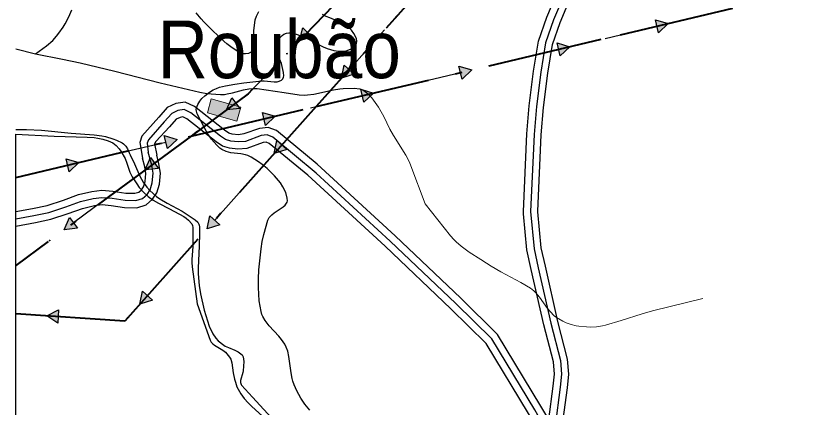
# Model space of a CAD drawing. Extents: x -64005 to -55000, y -89025 to -80000.
# Drawn here: x -64000 to -62912, y -85720 to -85176 of the extents above; entities that cross this region are included whole.
import ezdxf
from ezdxf.enums import TextEntityAlignment as Align

# ---------------------------------------------------------------- set-up
doc = ezdxf.new("R2010")
doc.units = 0
doc.header["$LTSCALE"] = 32
doc.linetypes.add('DOT_DASHED', pattern=[7.7, 5, -1.2, 0.3, -1.2])
doc.linetypes.add('LONG_DASHED', pattern=[7.5, 6, -1.5])
for name, color, linetype, lineweight in [('18', 7, 'Continuous', 25), ('2', 7, 'Continuous', 25), ('24', 7, 'Continuous', 25), ('39', 7, 'LONG_DASHED', 25), ('7', 7, 'Continuous', 13), ('8', 7, 'Continuous', 25)]:
    doc.layers.add(name, color=color, linetype=linetype, lineweight=lineweight)
doc.layers.add('45', color=7, linetype='Continuous')

msp = doc.modelspace()

# ---------------------------------------------------------------- hatches: boundary and pattern name
at = {"layer": '18'}
for points in [[(-63112.58, -85182.02), (-63094.86, -85187.34), (-63108.33, -85200.03)], [(-63588.59, -85206.01), (-63606.37, -85211.13), (-63601.91, -85193.17)], [(-63248.84, -85214.18), (-63231.12, -85219.5), (-63244.59, -85232.19)], [(-63530.68, -85257.56), (-63548.25, -85263.37), (-63544.49, -85245.25)], [(-63385.09, -85246.34), (-63367.38, -85251.66), (-63380.84, -85264.34)], [(-63521.35, -85278.49), (-63503.63, -85283.82), (-63517.1, -85296.5)], [(-63689.25, -85305.16), (-63707.63, -85307.24), (-63700.24, -85290.28)], [(-63657.61, -85310.65), (-63639.89, -85315.97), (-63653.36, -85328.65)], [(-63793.87, -85342.8), (-63776.15, -85348.12), (-63789.62, -85360.8)], [(-63623.84, -85362.07), (-63641.41, -85367.87), (-63637.65, -85349.76)], [(-63930.12, -85374.95), (-63912.41, -85380.28), (-63925.87, -85392.96)], [(-63801.85, -85388.35), (-63820.23, -85390.43), (-63812.85, -85373.47)], [(-63914.45, -85471.55), (-63932.84, -85473.63), (-63925.45, -85456.67)], [(-63717, -85466.57), (-63734.57, -85472.37), (-63730.81, -85454.26)], [(-63810.17, -85571.07), (-63827.73, -85576.88), (-63823.98, -85558.76)], [(-63941.65, -85603.3), (-63957.02, -85593), (-63940.42, -85584.84)]]:
    msp.add_hatch(color=256, dxfattribs=at).paths.add_polyline_path(points)
at = {"layer": '7'}
msp.add_hatch(color=256, dxfattribs=at).paths.add_polyline_path([(-63687.75, -85303.56), (-63728.64, -85291.98), (-63734.09, -85311.22), (-63693.2, -85322.8)])

# ---------------------------------------------------------------- linework, layer by layer
at = {"layer": '18'}
for p, q in [((-63543.92, -85146.32), (-63595.25, -85199.59)), ((-63488.36, -85196.18), (-63537.59, -85251.41)), ((-63318.71, -85240.18), (-63246.71, -85223.18)), ((-63454.97, -85272.33), (-63382.97, -85255.34)), ((-63727.49, -85336.64), (-63655.48, -85319.65)), ((-63863.74, -85368.79), (-63791.74, -85351.8)), ((-64000, -85400.95), (-63928, -85383.96)), ((-63674.68, -85405.19), (-63723.91, -85460.42)), ((-63860.45, -85420.14), (-63919.95, -85464.11)), ((-63973.05, -85503.34), (-64000, -85523.25)), ((-63767.84, -85509.7), (-63817.07, -85564.92)), ((-63867.22, -85598.99), (-63941.03, -85594.07))]:
    msp.add_line(p, q, dxfattribs=at)
at = {"layer": '18', "linetype": 'DOT_DASHED', "lineweight": 40}
for points in [[(-62369.26, -83445.65), (-62236.29, -83546.11), (-62227.39, -83552.83), (-62158.46, -83621.75), (-62183.05, -83848.43), (-62289.57, -83955.78), (-62419.8, -84087.01), (-63204.55, -84877.81), (-63379.7, -85074.29), (-63583.22, -85302.6), (-63848.56, -85600.24), (-64000, -85590.13)], [(-62600.64, -83578.59), (-62627.36, -83673.57), (-62637.7, -84129.6), (-62639.47, -84207.74), (-63103.07, -84688.84), (-63500.32, -85101.08), (-63677.61, -85285.06), (-63756.78, -85343.55), (-64000, -85523.25)], [(-64000, -85400.95), (-63756.78, -85343.55), (-63583.22, -85302.6), (-63160.94, -85202.94), (-62774.07, -85111.63), (-62063.05, -84888.71), (-61746.39, -84828.12), (-61731.7, -84825.31), (-61594.06, -84786.87), (-61360.14, -84721.55), (-60481.8, -84478.68), (-59562.86, -84105.04), (-59208.4, -83960.92), (-58840.52, -84105.61)]]:
    msp.add_lwpolyline(points, dxfattribs=at)
at = {"layer": '18'}
for points in [[(-63112.58, -85182.02), (-63094.86, -85187.34), (-63108.33, -85200.03)], [(-63588.59, -85206.01), (-63606.37, -85211.13), (-63601.91, -85193.17)], [(-63248.84, -85214.18), (-63231.12, -85219.5), (-63244.59, -85232.19)], [(-63530.68, -85257.56), (-63548.25, -85263.37), (-63544.49, -85245.25)], [(-63385.09, -85246.34), (-63367.38, -85251.66), (-63380.84, -85264.34)], [(-63521.35, -85278.49), (-63503.63, -85283.82), (-63517.1, -85296.5)], [(-63689.25, -85305.16), (-63707.63, -85307.24), (-63700.24, -85290.28)], [(-63657.61, -85310.65), (-63639.89, -85315.97), (-63653.36, -85328.65)], [(-63793.87, -85342.8), (-63776.15, -85348.12), (-63789.62, -85360.8)], [(-63623.84, -85362.07), (-63641.41, -85367.87), (-63637.65, -85349.76)], [(-63930.12, -85374.95), (-63912.41, -85380.28), (-63925.87, -85392.96)], [(-63801.85, -85388.35), (-63820.23, -85390.43), (-63812.85, -85373.47)], [(-63914.45, -85471.55), (-63932.84, -85473.63), (-63925.45, -85456.67)], [(-63717, -85466.57), (-63734.57, -85472.37), (-63730.81, -85454.26)], [(-63810.17, -85571.07), (-63827.73, -85576.88), (-63823.98, -85558.76)], [(-63941.65, -85603.3), (-63957.02, -85593), (-63940.42, -85584.84)]]:
    msp.add_lwpolyline(points, close=True, dxfattribs=at)
for points in [[(-63182.46, -85208.02), (-63160.94, -85202.94), (-63110.45, -85191.02)], [(-63641.06, -85247.13), (-63677.61, -85285.06), (-63694.75, -85297.72)], [(-63591.23, -85304.49), (-63583.22, -85302.6), (-63519.22, -85287.5)], [(-63581.52, -85300.69), (-63583.22, -85302.6), (-63630.75, -85355.91)], [(-63747.85, -85336.95), (-63756.78, -85343.55), (-63807.35, -85380.91)]]:
    msp.add_lwpolyline(points, dxfattribs=at)
for centre in [(-63471.72, -85177.52), (-63070.53, -85181.6), (-63206.79, -85213.76), (-63623.71, -85229.13), (-63343.05, -85245.92), (-63564.88, -85282.03), (-63479.3, -85278.07), (-63615.56, -85310.23), (-63727.74, -85322.1), (-63751.82, -85342.38), (-63888.08, -85374.53), (-63658.04, -85386.53), (-63840.34, -85405.29), (-63952.94, -85488.48), (-63751.2, -85491.03), (-63981.96, -85591.34), (-63844.37, -85595.54)]:
    msp.add_circle(centre, 0.5, dxfattribs=at)
at = {"layer": '2'}
msp.add_line((-64000, -85222.42), (-63972.52, -85229.46), dxfattribs=at)
for points in [[(-63972.52, -85229.46), (-63957.24, -85218.27), (-63948.46, -85210.72), (-63943.24, -85205), (-63939.99, -85200.91), (-63934, -85192.18), (-63931.23, -85187.55), (-63926.36, -85178.12), (-63922.31, -85168.46)], [(-63972.52, -85229.46), (-63934.93, -85236.88), (-63910.67, -85242.04), (-63862.42, -85253.64), (-63799.49, -85269.67), (-63744.58, -85282.66), (-63735.07, -85284.37), (-63728.67, -85285.09), (-63715.92, -85285.84), (-63710.29, -85285.63), (-63706.54, -85285.11), (-63699.04, -85283.44), (-63684.04, -85279.27), (-63676.53, -85277.76), (-63669.02, -85277.3), (-63665.26, -85277.61), (-63627.57, -85283.15), (-63606.64, -85286.08), (-63599.88, -85286.53), (-63595.37, -85286.39), (-63586.35, -85285.26), (-63559.29, -85279.27), (-63550.27, -85277.88), (-63545.76, -85277.54), (-63530.42, -85277), (-63522.85, -85278.12), (-63518.01, -85279.99), (-63515.67, -85281.36), (-63512.3, -85284.06), (-63506.19, -85290.39)], [(-64000, -85334.63), (-63984.87, -85334.55), (-63964.19, -85335.42), (-63922.93, -85339.54), (-63891.15, -85341.8), (-63880.66, -85343.21), (-63875.45, -85344.25), (-63865.12, -85347.22), (-63860.01, -85349.25), (-63852.43, -85353.08), (-63850.49, -85354.41), (-63847.4, -85357.64), (-63845.04, -85361.41), (-63842.4, -85366.81), (-63841.04, -85369.48), (-63835.11, -85382.12), (-63827.74, -85399.12), (-63823.24, -85407.29), (-63817.86, -85414.65), (-63813.78, -85419.13), (-63804.73, -85427.26), (-63800.01, -85430.77), (-63790.02, -85436.78), (-63769.27, -85447.62), (-63759.27, -85454.03), (-63751.03, -85459.87), (-63747.52, -85463.21), (-63745.87, -85465.74), (-63745.32, -85467.12), (-63744.93, -85469.34), (-63744.83, -85478.37), (-63745.64, -85496.45), (-63747.06, -85526.41), (-63747.04, -85534.6), (-63745.66, -85550.98), (-63743.84, -85562.5), (-63738.54, -85585.22), (-63734.16, -85600.08), (-63731.44, -85607.32), (-63726.44, -85618.03), (-63722.34, -85624.08), (-63719.04, -85627.59), (-63711.49, -85633.73), (-63709.42, -85635.06), (-63705.03, -85637.15), (-63695.91, -85640.66), (-63691.55, -85643), (-63687.66, -85645.66), (-63686, -85647.22), (-63684.43, -85650.13), (-63683.66, -85656.54), (-63684.43, -85669.39), (-63684.74, -85671.66), (-63687.94, -85682.56), (-63688.12, -85685.46), (-63687.38, -85688.14), (-63686.57, -85689.36), (-63671.62, -85705.77), (-63640.29, -85740)]]:
    msp.add_lwpolyline(points, dxfattribs=at)
at = {"layer": '2', "lineweight": 13}
msp.add_lwpolyline([(-63046.65, -85568.95), (-63116.44, -85586.08), (-63131.11, -85590.11), (-63160.11, -85599.43), (-63181.94, -85606.06), (-63185.94, -85607.01), (-63194.12, -85608.21), (-63202.42, -85608.59), (-63207.97, -85608.47), (-63218.97, -85607.49), (-63222.57, -85606.93), (-63229.63, -85605.21), (-63236.5, -85602.69), (-63240.96, -85600.59), (-63249.59, -85595.37), (-63252.92, -85592.8), (-63258.76, -85586.98), (-63262.22, -85582.74), (-63273.3, -85567.27), (-63278.41, -85561.16), (-63281.22, -85558.38), (-63285.9, -85554.71), (-63299.2, -85546.58), (-63326.89, -85531.78), (-63340.53, -85523.99), (-63347.13, -85519.76), (-63354.95, -85514.68), (-63370.79, -85504.6), (-63382.16, -85496.45), (-63389.16, -85490.44), (-63392.43, -85487.19), (-63396.97, -85481.97), (-63431.86, -85437.74), (-63451.88, -85384.62), (-63453.94, -85379.67), (-63458.86, -85370.15), (-63476.04, -85342.73), (-63480.83, -85333.9), (-63489.39, -85316.3), (-63496.63, -85303.24), (-63506.19, -85290.39)], dxfattribs=at)
at = {"layer": '24'}
for points in [[(-63663.37, -85171.32), (-63666.6, -85177.59), (-63668.11, -85182.81), (-63670.11, -85196.81), (-63669.93, -85213.21), (-63670.33, -85217.89), (-63671.4, -85222.52), (-63672.27, -85224.82), (-63673.38, -85226.54), (-63674.39, -85227.45), (-63676.89, -85228.75), (-63681.39, -85229.48), (-63684.85, -85229.2), (-63687.43, -85228.52), (-63689.9, -85227.34), (-63701.36, -85219.58), (-63707, -85215.33), (-63715.09, -85208.45), (-63731.22, -85193.05), (-63739.02, -85185.15), (-63742.77, -85181.04), (-63749.72, -85172.32)], [(-63638.83, -85218.72), (-63637.86, -85214.28), (-63636.02, -85210.34), (-63633.17, -85206.52), (-63630.27, -85203.74), (-63628.08, -85202.25), (-63624.3, -85200.74), (-63621.2, -85200.27), (-63618.84, -85200.29), (-63614.09, -85201.05), (-63609.39, -85202.49), (-63596.56, -85207.53), (-63573.28, -85219.67), (-63567.95, -85221.96), (-63558.85, -85224.61), (-63555.56, -85225.2), (-63550.59, -85225.7), (-63545.64, -85225.67), (-63541.39, -85225.11), (-63535.52, -85222.97), (-63531.32, -85220.3), (-63528.04, -85217.03), (-63527.12, -85215.15), (-63526.72, -85211.63), (-63527.29, -85208.56), (-63528.92, -85204.56), (-63530.82, -85201.35), (-63534.37, -85196.76), (-63537.04, -85193.98), (-63542.56, -85189.54), (-63548.8, -85186.07), (-63564.38, -85179.65), (-63569.44, -85177.39), (-63574.26, -85174.72)], [(-63592.16, -85723.99), (-63598.7, -85715.79), (-63604.39, -85707.22), (-63609.85, -85697.25), (-63613.7, -85688.91), (-63615.65, -85683.52), (-63616.63, -85679.83), (-63618.05, -85672.27), (-63620.95, -85649.36), (-63622.62, -85642.07), (-63624.64, -85636.46), (-63626.73, -85632.43), (-63631.12, -85626.08), (-63635.21, -85621.23), (-63648.35, -85606.99), (-63654.09, -85599.49), (-63657.13, -85594.14), (-63658.34, -85591.34), (-63659.67, -85586.92), (-63662.21, -85571.98), (-63663.4, -85553.77), (-63663.3, -85541.55), (-63662.66, -85529.32), (-63659.64, -85500.02), (-63657.93, -85489.95), (-63655.73, -85479.94), (-63650.22, -85460.34), (-63648.29, -85456.57), (-63644.9, -85452.89), (-63641.55, -85450.23), (-63629.02, -85441.84), (-63626.22, -85439.4), (-63624.2, -85436.81), (-63623.56, -85435.44), (-63623.16, -85433.26), (-63623.39, -85429.69), (-63625.5, -85421.98), (-63629.41, -85413.91), (-63632.8, -85408.57), (-63635.31, -85405.11), (-63640.79, -85398.63), (-63651.19, -85388.58), (-63658.33, -85382.83), (-63663.23, -85379.32), (-63673.53, -85372.81), (-63678.05, -85370.7), (-63681.24, -85369.71), (-63687.89, -85368.41), (-63701.54, -85366.62), (-63708.1, -85365.02), (-63714.19, -85362.23), (-63716.99, -85360.21), (-63721.18, -85356.37), (-63728.31, -85348), (-63734.24, -85338.88), (-63748.08, -85312.56), (-63749.21, -85309.12), (-63749.48, -85306.87), (-63749.1, -85304.17), (-63747.26, -85299.79), (-63744.42, -85295.13), (-63741.6, -85291.6), (-63737.52, -85287.5), (-63731.3, -85282.67), (-63725.86, -85279.44), (-63721.61, -85277.44), (-63717.27, -85275.85), (-63708.8, -85273.68), (-63696.22, -85271.32), (-63683.63, -85269.64), (-63658.42, -85267.01), (-63655.42, -85266.9), (-63641.29, -85268.46), (-63637.28, -85268.15), (-63634.62, -85267.42), (-63631.34, -85265.74), (-63629.55, -85264.11), (-63628.4, -85261.94), (-63628, -85259.99), (-63628.33, -85255.17), (-63631.36, -85243), (-63637.84, -85227.46), (-63638.9, -85222.29), (-63638.83, -85218.72)], [(-63972.31, -87227.87), (-63975.53, -87229.32), (-64000, -87237.1), (-64000, -85340.91)], [(-64000, -85340.91), (-63946.82, -85343.87), (-63900.86, -85345.13), (-63891.04, -85345.72), (-63886.16, -85346.29), (-63878.9, -85347.68), (-63871.69, -85349.92), (-63865.33, -85352.91), (-63860.52, -85356.65), (-63856.49, -85361.19), (-63854.13, -85364.53), (-63848.25, -85374.62), (-63845.78, -85380.97), (-63841.51, -85393.83), (-63838.51, -85399.9), (-63832.03, -85409.89), (-63828.52, -85414.68), (-63822.77, -85421.42), (-63816.27, -85427.45), (-63809.1, -85432.47), (-63801.74, -85436.66), (-63786.71, -85444.29), (-63766.99, -85455.23), (-63763.62, -85457.46), (-63760.4, -85460.08), (-63755.85, -85465.3), (-63754.81, -85467.74), (-63754.32, -85470.28), (-63754.13, -85475.46), (-63754.13, -85496.87), (-63755.62, -85514.75), (-63755.77, -85518.94), (-63755.39, -85525.21), (-63748.47, -85576.21), (-63730.21, -85626.59), (-63728.76, -85629.36), (-63726.46, -85631.91), (-63724.21, -85633.65), (-63712.46, -85640.47), (-63709, -85643.22), (-63703.48, -85650.4), (-63701.78, -85653.33), (-63699.98, -85658.07), (-63698.1, -85671.93), (-63696.34, -85680.69), (-63695.26, -85685.03), (-63693.06, -85691.45), (-63691.47, -85694.93), (-63687.7, -85701.48), (-63683.27, -85707.56), (-63677.72, -85713.82), (-63672.91, -85718.52), (-63657.12, -85732.6)]]:
    msp.add_lwpolyline(points, dxfattribs=at)
at = {"layer": '39'}
for points in [[(-63241.08, -85151.48), (-63254.08, -85182.26), (-63265.23, -85214.1), (-63271.6, -85254.69), (-63277.71, -85302.71), (-63280.89, -85341.17), (-63285.66, -85448.09), (-63280.88, -85500.08), (-63275.05, -85526.35), (-63257.81, -85603.02), (-63244.28, -85655.02), (-63242.69, -85673.85), (-63244.55, -85691.89), (-63251.71, -85746.02)], [(-63583.07, -85394.9), (-63643.43, -85344.82), (-63651.14, -85341.98), (-63659.26, -85342.79), (-63681.18, -85350.91), (-63691.33, -85351.73), (-63701.47, -85350.51), (-63708.78, -85348.48), (-63716.09, -85343.6), (-63757.08, -85311.12), (-63766.42, -85306.65), (-63774.94, -85307.87), (-63783.58, -85312.13), (-63794.06, -85323.85), (-63815.96, -85348.53), (-63817.5, -85353.47), (-63816.04, -85365.74)], [(-64000, -85458.45), (-63974.64, -85453.86), (-63953.86, -85449.41), (-63930.6, -85441.74), (-63910.07, -85434.3), (-63892.5, -85430.09), (-63880.38, -85428.61), (-63866.28, -85429.85), (-63848.21, -85432.57), (-63833.36, -85433.05), (-63823.96, -85430.08), (-63817.77, -85424.64), (-63813.57, -85418.21), (-63810.6, -85408.31), (-63809.36, -85395.19), (-63811.09, -85384.05), (-63816.04, -85365.74)], [(-63253.9, -85768.32), (-63280.08, -85723.39), (-63339.56, -85625.07), (-63389.57, -85575.91), (-63480.62, -85489.18), (-63583.07, -85394.9)]]:
    msp.add_lwpolyline(points, dxfattribs=at)
at = {"layer": '7'}
msp.add_lwpolyline([(-63687.75, -85303.56), (-63728.64, -85291.98), (-63734.09, -85311.22), (-63693.2, -85322.8)], close=True, dxfattribs=at)
at = {"layer": '8', "linetype": 'LONG_DASHED'}
for points in [[(-63260.6, -85736.96), (-63254.48, -85690.72), (-63252.73, -85673.76), (-63254.17, -85656.71), (-63267.53, -85605.38), (-63284.81, -85528.54), (-63290.78, -85501.64), (-63295.41, -85451.26), (-63295.68, -85448.33), (-63290.87, -85340.53), (-63287.66, -85301.67), (-63281.51, -85253.28), (-63274.97, -85211.65), (-63263.41, -85178.66), (-63250.54, -85148.18)], [(-63582.03, -85382.29), (-63638.39, -85336.02), (-63649.84, -85331.8), (-63661.66, -85332.98), (-63683.61, -85340.36), (-63690.73, -85341.73), (-63699.52, -85340.67), (-63704.56, -85339.27), (-63710.2, -85335.51), (-63751.75, -85302.58), (-63764.84, -85296.32), (-63777.93, -85298.2), (-63789.74, -85304.02), (-63801.53, -85317.2), (-63824.87, -85343.5), (-63827.68, -85352.53), (-63823.95, -85374.34)], [(-64000, -85448.29), (-63976.58, -85444.05), (-63956.48, -85439.74), (-63933.87, -85432.29), (-63912.95, -85424.71), (-63894.28, -85420.23), (-63880.55, -85418.56), (-63865.1, -85419.92), (-63847.3, -85422.59), (-63834.74, -85423), (-63828.98, -85421.18), (-63825.4, -85418.03), (-63822.73, -85413.95), (-63820.46, -85406.38), (-63819.43, -85395.49), (-63820.89, -85386.08), (-63823.95, -85374.34)], [(-63260.6, -85736.96), (-63271.48, -85718.28), (-63331.65, -85618.82), (-63382.62, -85568.72), (-63473.78, -85481.88), (-63582.03, -85382.29)]]:
    msp.add_lwpolyline(points, dxfattribs=at)
at = {"layer": '8'}
for points in [[(-63241.77, -85747.16), (-63234.62, -85693.06), (-63232.65, -85673.94), (-63234.39, -85653.33), (-63248.09, -85600.66), (-63265.29, -85524.17), (-63270.98, -85498.53), (-63275.58, -85448.53), (-63275.64, -85447.85), (-63270.91, -85341.81), (-63267.76, -85303.75), (-63261.7, -85256.09), (-63255.49, -85216.55), (-63244.75, -85185.86), (-63231.62, -85154.79)], [(-63594.73, -85397.75), (-63648.47, -85353.62), (-63652.44, -85352.16), (-63656.86, -85352.6), (-63679.55, -85360.66), (-63691.93, -85361.73), (-63703.42, -85360.35), (-63713, -85357.69), (-63721.98, -85351.69), (-63762.41, -85319.66), (-63768, -85316.98), (-63771.95, -85317.54), (-63777.42, -85320.24), (-63786.59, -85330.5), (-63805.79, -85350.91), (-63807.32, -85354.41), (-63804.42, -85369.97)], [(-64000, -85468.61), (-63972.7, -85463.68), (-63951.24, -85459.08), (-63927.33, -85451.19), (-63907.19, -85443.89), (-63890.72, -85439.95), (-63880.21, -85438.66), (-63867.46, -85439.78), (-63849.12, -85442.55), (-63831.98, -85443.1), (-63818.94, -85438.98), (-63810.14, -85431.25), (-63804.41, -85422.47), (-63800.74, -85410.24), (-63799.29, -85394.89), (-63801.29, -85382.02), (-63804.42, -85369.97)], [(-63276.18, -85749.95), (-63288.68, -85728.5), (-63347.47, -85631.32), (-63396.52, -85583.11), (-63487.46, -85496.48), (-63594.73, -85397.75)]]:
    msp.add_lwpolyline(points, dxfattribs=at)

# ---------------------------------------------------------------- texts
at = {"layer": '45', "width": 0.9}
msp.add_text('Roubão', height=80, rotation=0.008, dxfattribs=at).set_placement((-63634.4, -85263.17), align=Align.CENTER)

doc.saveas('drawing.dxf')
